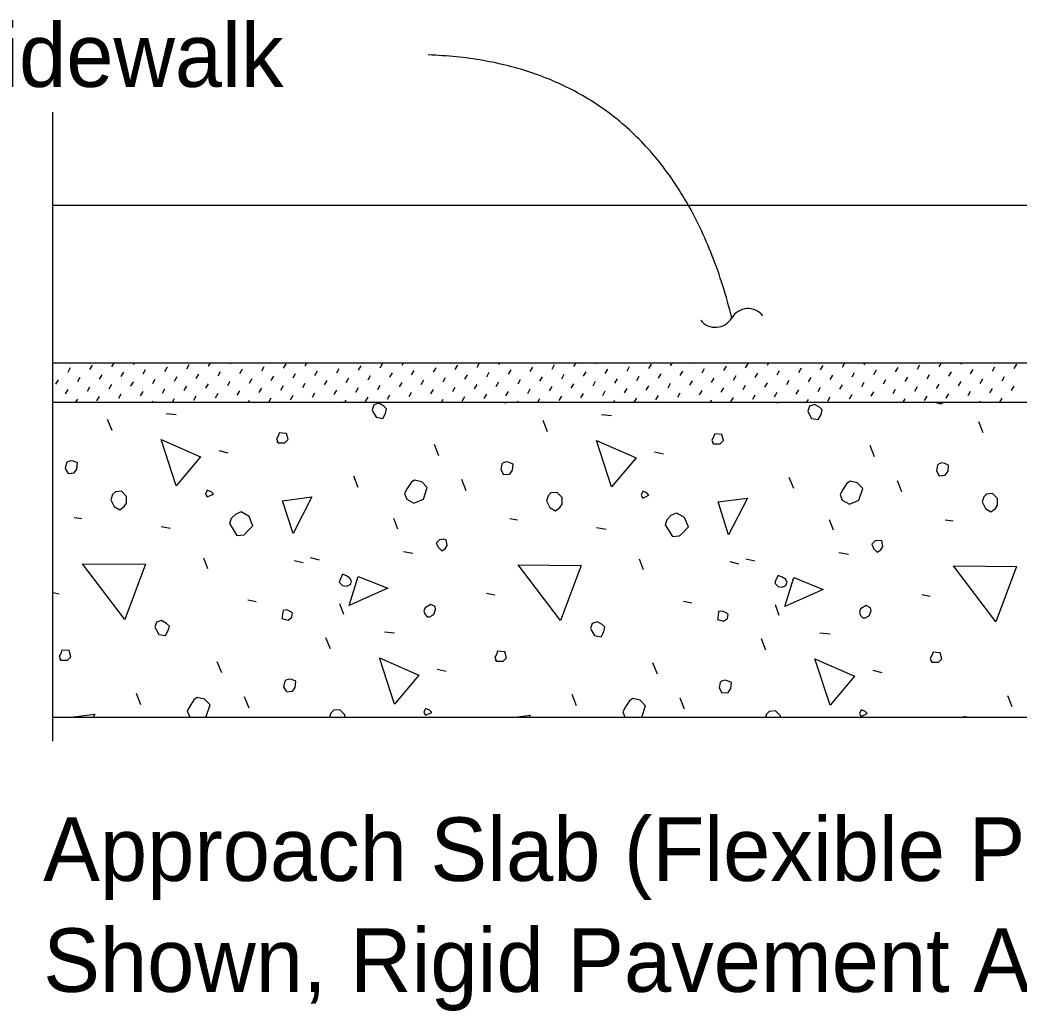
# Model space of a CAD drawing. Extents: x 0 to 40.8, y 1 to 28.
# Drawn here: x 23.621 to 26.792, y 9.097 to 12.242 of the extents above; entities that cross this region are included whole.
import ezdxf

# ---------------------------------------------------------------- set-up
doc = ezdxf.new("R2010")
doc.units = 0
for name, color, linetype in [('Dimension', 7, 'Continuous'), ('Miscellaneous', 7, 'Continuous'), ('TextStructures', 7, 'Continuous'), ('TrafBarrierConc', 7, 'Continuous')]:
    doc.layers.add(name, color=color, linetype=linetype)

msp = doc.modelspace()

# ---------------------------------------------------------------- linework, layer by layer
at = {"layer": 'Dimension'}
msp.add_lwpolyline([(23.7254, 9.9535), (23.7254, 11.9492)], dxfattribs=at)
for centre, start, end in [((25.9315, 11.2668), 38.2646, 149.9919), ((25.8282, 11.3265), 218.2646, 329.9919)]:
    msp.add_arc(centre, 0.0596, start, end, dxfattribs=at)
msp.add_open_spline([(25.8806, 11.2968), (25.6769, 12.1034), (24.917, 12.1314)], degree=2, dxfattribs=at)
at = {"layer": 'Miscellaneous'}
for p, q in [((23.7737, 11.1251), (23.7818, 11.1391)), ((23.8429, 11.1332), (23.851, 11.1472)), ((23.9121, 11.1413), (23.9197, 11.1545)), ((23.9812, 11.1494), (23.9842, 11.1545)), ((24.0117, 11.1189), (24.0198, 11.1328)), ((24.0809, 11.127), (24.089, 11.141)), ((24.1501, 11.1351), (24.1582, 11.1491)), ((24.2192, 11.1432), (24.2258, 11.1545)), ((24.2884, 11.1513), (24.2903, 11.1545)), ((24.3189, 11.1207), (24.327, 11.1347)), ((24.3881, 11.1288), (24.3962, 11.1428)), ((24.4573, 11.1369), (24.4654, 11.1509)), ((24.5264, 11.145), (24.5319, 11.1545)), ((24.5956, 11.1531), (24.5964, 11.1545)), ((24.6261, 11.1226), (24.6342, 11.1366)), ((24.6953, 11.1307), (24.7034, 11.1447)), ((24.7644, 11.1388), (24.7726, 11.1528)), ((24.8336, 11.1469), (24.838, 11.1545)), ((24.8641, 11.1164), (24.8722, 11.1304)), ((24.9333, 11.1245), (24.9414, 11.1385)), ((25.0025, 11.1326), (25.0106, 11.1466)), ((25.0716, 11.1407), (25.0796, 11.1545)), ((25.1408, 11.1488), (25.1441, 11.1545)), ((25.1713, 11.1183), (25.1794, 11.1323)), ((25.2405, 11.1264), (25.2486, 11.1404)), ((25.3097, 11.1345), (25.3178, 11.1485)), ((25.3788, 11.1426), (25.3857, 11.1545)), ((25.448, 11.1507), (25.4502, 11.1545)), ((25.4785, 11.1201), (25.4866, 11.1341)), ((25.5477, 11.1282), (25.5558, 11.1422)), ((25.6168, 11.1363), (25.6249, 11.1503)), ((25.686, 11.1444), (25.6918, 11.1545)), ((25.7552, 11.1526), (25.7563, 11.1545)), ((25.7857, 11.122), (25.7938, 11.136)), ((25.8549, 11.1301), (25.863, 11.1441)), ((25.924, 11.1382), (25.9321, 11.1522)), ((25.9932, 11.1463), (25.9979, 11.1545)), ((26.0237, 11.1158), (26.0318, 11.1298)), ((26.0624, 11.1544), (26.0624, 11.1545)), ((26.0929, 11.1239), (26.101, 11.1379)), ((26.1621, 11.132), (26.1702, 11.146)), ((26.2312, 11.1401), (26.2393, 11.1541)), ((26.3004, 11.1482), (26.304, 11.1545)), ((26.3309, 11.1177), (26.339, 11.1317)), ((26.4001, 11.1258), (26.4082, 11.1398)), ((26.4692, 11.1339), (26.4773, 11.1479)), ((26.5384, 11.142), (26.5457, 11.1545)), ((26.6076, 11.1501), (26.6101, 11.1545)), ((26.6381, 11.1196), (26.6462, 11.1335)), ((26.7073, 11.1277), (26.7154, 11.1417)), ((26.7764, 11.1358), (26.7845, 11.1498)), ((23.7351, 11.0864), (23.7432, 11.1004)), ((23.8043, 11.0945), (23.8124, 11.1085)), ((23.8734, 11.1026), (23.8815, 11.1166)), ((23.9426, 11.1108), (23.9507, 11.1247)), ((24.0423, 11.0883), (24.0504, 11.1023)), ((24.1114, 11.0964), (24.1195, 11.1104)), ((24.1806, 11.1045), (24.1887, 11.1185)), ((24.2498, 11.1126), (24.2579, 11.1266)), ((24.3495, 11.0902), (24.3576, 11.1042)), ((24.4186, 11.0983), (24.4267, 11.1123)), ((24.4878, 11.1064), (24.4959, 11.1204)), ((24.557, 11.1145), (24.5651, 11.1285)), ((24.5875, 11.084), (24.5956, 11.098)), ((24.6567, 11.0921), (24.6648, 11.1061)), ((24.7258, 11.1002), (24.7339, 11.1142)), ((24.795, 11.1083), (24.8031, 11.1223)), ((24.8947, 11.0859), (24.9028, 11.0998)), ((24.9638, 11.094), (24.9719, 11.108)), ((25.033, 11.1021), (25.0411, 11.1161)), ((25.1022, 11.1102), (25.1103, 11.1242)), ((25.2019, 11.0877), (25.21, 11.1017)), ((25.271, 11.0958), (25.2791, 11.1098)), ((25.3402, 11.1039), (25.3483, 11.1179)), ((25.4094, 11.112), (25.4175, 11.126)), ((25.509, 11.0896), (25.5171, 11.1036)), ((25.5782, 11.0977), (25.5863, 11.1117)), ((25.6474, 11.1058), (25.6555, 11.1198)), ((25.7165, 11.1139), (25.7246, 11.1279)), ((25.8162, 11.0915), (25.8243, 11.1055)), ((25.8854, 11.0996), (25.8935, 11.1136)), ((25.9546, 11.1077), (25.9627, 11.1217)), ((26.0543, 11.0853), (26.0624, 11.0993)), ((26.1234, 11.0934), (26.1315, 11.1074)), ((26.1926, 11.1015), (26.2007, 11.1155)), ((26.2617, 11.1096), (26.2698, 11.1236)), ((26.3614, 11.0871), (26.3695, 11.1011)), ((26.4306, 11.0952), (26.4387, 11.1092)), ((26.4998, 11.1033), (26.5079, 11.1173)), ((26.5689, 11.1115), (26.577, 11.1254)), ((26.6686, 11.089), (26.6767, 11.103)), ((26.7378, 11.0971), (26.7459, 11.1111)), ((23.7656, 11.0559), (23.7737, 11.0699)), ((23.8348, 11.064), (23.8429, 11.078)), ((23.904, 11.0721), (23.9121, 11.0861)), ((23.9731, 11.0802), (23.9812, 11.0942)), ((24.0728, 11.0578), (24.0809, 11.0718)), ((24.142, 11.0659), (24.1501, 11.0799)), ((24.2111, 11.074), (24.2192, 11.088)), ((24.2803, 11.0821), (24.2884, 11.0961)), ((24.38, 11.0597), (24.3881, 11.0737)), ((24.4492, 11.0678), (24.4573, 11.0818)), ((24.5183, 11.0759), (24.5264, 11.0899)), ((24.618, 11.0534), (24.6261, 11.0674)), ((24.6872, 11.0615), (24.6953, 11.0755)), ((24.7563, 11.0697), (24.7644, 11.0836)), ((24.8255, 11.0778), (24.8336, 11.0917)), ((24.9252, 11.0553), (24.9333, 11.0693)), ((24.9944, 11.0634), (25.0025, 11.0774)), ((25.0635, 11.0715), (25.0716, 11.0855)), ((25.1327, 11.0796), (25.1408, 11.0936)), ((25.2324, 11.0572), (25.2405, 11.0712)), ((25.3016, 11.0653), (25.3097, 11.0793)), ((25.3707, 11.0734), (25.3788, 11.0874)), ((25.4399, 11.0815), (25.448, 11.0955)), ((25.5396, 11.0591), (25.5477, 11.0731)), ((25.6087, 11.0672), (25.6168, 11.0812)), ((25.6779, 11.0753), (25.686, 11.0893)), ((25.7471, 11.0834), (25.7552, 11.0974)), ((25.7776, 11.0529), (25.7857, 11.0669)), ((25.8468, 11.061), (25.8549, 11.075)), ((25.9159, 11.0691), (25.924, 11.0831)), ((25.9851, 11.0772), (25.9932, 11.0912)), ((26.0848, 11.0547), (26.0929, 11.0687)), ((26.1539, 11.0628), (26.1621, 11.0768)), ((26.2231, 11.0709), (26.2312, 11.0849)), ((26.2923, 11.079), (26.3004, 11.093)), ((26.392, 11.0566), (26.4001, 11.0706)), ((26.4611, 11.0647), (26.4692, 11.0787)), ((26.5303, 11.0728), (26.5384, 11.0868)), ((26.5995, 11.0809), (26.6076, 11.0949)), ((26.6992, 11.0585), (26.7073, 11.0725)), ((26.7683, 11.0666), (26.7764, 11.0806)), ((23.7985, 11.0295), (23.8043, 11.0394)), ((23.8653, 11.0335), (23.8734, 11.0475)), ((23.9345, 11.0416), (23.9426, 11.0556)), ((24.0036, 11.0497), (24.0117, 11.0637)), ((24.1046, 11.0295), (24.1114, 11.0413)), ((24.1725, 11.0354), (24.1806, 11.0494)), ((24.2417, 11.0435), (24.2498, 11.0575)), ((24.3108, 11.0516), (24.3189, 11.0656)), ((24.3463, 11.0295), (24.3495, 11.035)), ((24.4107, 11.0295), (24.4186, 11.0431)), ((24.4797, 11.0372), (24.4878, 11.0512)), ((24.5489, 11.0453), (24.557, 11.0593)), ((24.6524, 11.0295), (24.6567, 11.0369)), ((24.7177, 11.031), (24.7258, 11.045)), ((24.7869, 11.0391), (24.795, 11.0531)), ((24.856, 11.0472), (24.8641, 11.0612)), ((24.9585, 11.0295), (24.9638, 11.0388)), ((25.0249, 11.0329), (25.033, 11.0469)), ((25.0941, 11.041), (25.1022, 11.055)), ((25.1632, 11.0491), (25.1713, 11.0631)), ((25.2646, 11.0295), (25.271, 11.0407)), ((25.3321, 11.0348), (25.3402, 11.0488)), ((25.4012, 11.0429), (25.4094, 11.0569)), ((25.4704, 11.051), (25.4785, 11.065)), ((25.5062, 11.0295), (25.509, 11.0344)), ((25.5707, 11.0295), (25.5782, 11.0425)), ((25.6393, 11.0367), (25.6474, 11.0506)), ((25.7084, 11.0448), (25.7165, 11.0587)), ((25.8123, 11.0295), (25.8162, 11.0363)), ((25.8773, 11.0304), (25.8854, 11.0444)), ((25.9465, 11.0385), (25.9546, 11.0525)), ((26.0156, 11.0466), (26.0237, 11.0606)), ((26.1184, 11.0295), (26.1234, 11.0382)), ((26.1845, 11.0323), (26.1926, 11.0463)), ((26.2536, 11.0404), (26.2617, 11.0544)), ((26.3228, 11.0485), (26.3309, 11.0625)), ((26.4245, 11.0295), (26.4306, 11.0401)), ((26.4917, 11.0342), (26.4998, 11.0482)), ((26.5608, 11.0423), (26.5689, 11.0563)), ((26.63, 11.0504), (26.6381, 11.0644)), ((26.7306, 11.0295), (26.7378, 11.042)), ((23.7341, 11.0295), (23.7351, 11.0313)), ((24.0402, 11.0295), (24.0423, 11.0332)), ((24.894, 11.0295), (24.8947, 11.0307)), ((25.2001, 11.0295), (25.2019, 11.0326)), ((26.0539, 11.0295), (26.0543, 11.0301)), ((26.36, 11.0295), (26.3614, 11.032)), ((26.6661, 11.0295), (26.6686, 11.0339)), ((23.9131, 10.9391), (23.899, 10.9745)), ((24.0846, 10.9939), (24.1164, 10.9904)), ((25.2955, 10.9356), (25.2814, 10.971)), ((25.467, 10.9904), (25.4988, 10.9869)), ((26.6779, 10.9321), (26.6638, 10.9674)), ((24.2525, 10.8755), (24.2808, 10.8684)), ((24.9508, 10.8596), (24.9366, 10.895)), ((26.3332, 10.8561), (26.319, 10.8914)), ((25.6349, 10.872), (25.6632, 10.8649)), ((24.6945, 10.7588), (24.6803, 10.7942)), ((25.0374, 10.7482), (25.0233, 10.7836)), ((26.0769, 10.7553), (26.0627, 10.7907)), ((26.4198, 10.7447), (26.4057, 10.78)), ((23.7929, 10.6634), (23.8177, 10.6598)), ((24.82, 10.6263), (24.8076, 10.6598)), ((25.1753, 10.6598), (25.2, 10.6563)), ((26.2024, 10.6227), (26.19, 10.6563)), ((26.5577, 10.6563), (26.5824, 10.6528)), ((24.0687, 10.6351), (24.0987, 10.6298)), ((25.4511, 10.6316), (25.4811, 10.6263)), ((24.2172, 10.5007), (24.2048, 10.5343)), ((24.4912, 10.5273), (24.5195, 10.5202)), ((24.5424, 10.5361), (24.5707, 10.529)), ((24.8377, 10.5555), (24.8677, 10.5502)), ((25.5996, 10.4972), (25.5872, 10.5308)), ((25.9248, 10.5326), (25.9531, 10.5255)), ((26.22, 10.552), (26.2501, 10.5467)), ((25.8736, 10.5237), (25.9018, 10.5166)), ((23.7254, 10.4251), (23.7452, 10.4212)), ((24.3444, 10.4017), (24.371, 10.3964)), ((25.1011, 10.423), (25.1276, 10.4177)), ((26.4834, 10.4194), (26.51, 10.4141)), ((24.6485, 10.3558), (24.6361, 10.3894)), ((25.7268, 10.3982), (25.7534, 10.3929)), ((26.0309, 10.3522), (26.0185, 10.3858)), ((24.6061, 10.2462), (24.5919, 10.2815)), ((24.7775, 10.301), (24.8094, 10.2974)), ((25.9885, 10.2426), (25.9743, 10.278)), ((26.1599, 10.2974), (26.1918, 10.2939)), ((24.2614, 10.1702), (24.2472, 10.2055)), ((24.9455, 10.1825), (24.9738, 10.1755)), ((25.6438, 10.1666), (25.6296, 10.202)), ((26.3279, 10.179), (26.3562, 10.1719)), ((24.005, 10.0694), (23.9909, 10.1048)), ((24.348, 10.0588), (24.3338, 10.0942)), ((25.3874, 10.0659), (25.3733, 10.1012)), ((25.7304, 10.0553), (25.7162, 10.0906)), ((26.7698, 10.0623), (26.7557, 10.0977))]:
    msp.add_line(p, q, dxfattribs=at)
for points in [[(24.6432, 11.0293), (24.643, 11.0295)], [(24.6433, 11.0295), (24.6432, 11.0293)], [(24.7422, 10.9975), (24.751, 10.9816), (24.7722, 10.978), (24.7811, 10.9939), (24.7846, 11.0081), (24.7758, 11.0169), (24.7599, 11.0258), (24.744, 11.0205), (24.7387, 11.0046), (24.7422, 10.9975)], [(25.1539, 11.0295), (25.1612, 11.0275), (25.1639, 11.0295)], [(26.0256, 11.0258), (26.0227, 11.0295)], [(26.027, 11.0295), (26.0256, 11.0258)], [(26.1246, 10.9939), (26.1334, 10.978), (26.1546, 10.9745), (26.1635, 10.9904), (26.167, 11.0046), (26.1582, 11.0134), (26.1423, 11.0222), (26.1264, 11.0169), (26.1211, 11.001), (26.1246, 10.9939)], [(26.5241, 11.0293), (26.5435, 11.024), (26.5513, 11.0295)], [(26.5241, 11.0295), (26.5241, 11.0293)], [(24.1164, 10.7641), (24.0687, 10.9109), (24.1942, 10.8561), (24.1164, 10.7641)], [(24.4399, 10.9003), (24.4611, 10.9003), (24.4717, 10.9109), (24.4664, 10.9303), (24.4434, 10.9321), (24.4399, 10.9215), (24.4346, 10.9126), (24.4399, 10.9003), (24.4364, 10.9038)], [(25.4988, 10.7606), (25.4511, 10.9073), (25.5766, 10.8525), (25.4988, 10.7606)], [(25.8223, 10.8967), (25.8435, 10.8967), (25.8541, 10.9073), (25.8488, 10.9268), (25.8258, 10.9285), (25.8223, 10.9179), (25.817, 10.9091), (25.8223, 10.8967), (25.8188, 10.9003)], [(23.7646, 10.8189), (23.7735, 10.803), (23.7929, 10.8048), (23.8017, 10.8172), (23.8035, 10.8366), (23.7911, 10.8419), (23.7823, 10.8437), (23.7717, 10.8402), (23.7682, 10.8366), (23.7646, 10.8189)], [(25.147, 10.8154), (25.1559, 10.7995), (25.1753, 10.8013), (25.1841, 10.8136), (25.1859, 10.8331), (25.1735, 10.8384), (25.1647, 10.8402), (25.1541, 10.8366), (25.1505, 10.8331), (25.147, 10.8154)], [(26.5294, 10.8119), (26.5382, 10.796), (26.5577, 10.7977), (26.5665, 10.8101), (26.5683, 10.8295), (26.5559, 10.8348), (26.5471, 10.8366), (26.5365, 10.8331), (26.5329, 10.8295), (26.5294, 10.8119)], [(24.8483, 10.7217), (24.8712, 10.7093), (24.9013, 10.7217), (24.9137, 10.7588), (24.896, 10.7765), (24.873, 10.7818), (24.8624, 10.7747), (24.85, 10.7553), (24.8412, 10.7394), (24.8483, 10.7217)], [(24.2154, 10.7288), (24.2348, 10.7376), (24.2278, 10.7447), (24.2154, 10.75), (24.2101, 10.7376), (24.2154, 10.7288)], [(26.2307, 10.7182), (26.2536, 10.7058), (26.2837, 10.7182), (26.2961, 10.7553), (26.2784, 10.773), (26.2554, 10.7783), (26.2448, 10.7712), (26.2324, 10.7518), (26.2236, 10.7359), (26.2307, 10.7182)], [(23.9096, 10.7199), (23.9202, 10.6987), (23.9379, 10.6881), (23.952, 10.6987), (23.9591, 10.7093), (23.9591, 10.7305), (23.9432, 10.7465), (23.9237, 10.7447), (23.9149, 10.7359), (23.9096, 10.7199)], [(24.4876, 10.6121), (24.454, 10.7164), (24.5477, 10.7288), (24.4876, 10.6121)], [(25.292, 10.7164), (25.3026, 10.6952), (25.3203, 10.6846), (25.3344, 10.6952), (25.3415, 10.7058), (25.3415, 10.727), (25.3256, 10.7429), (25.3061, 10.7412), (25.2973, 10.7323), (25.292, 10.7164)], [(25.5978, 10.7252), (25.6172, 10.7341), (25.6102, 10.7412), (25.5978, 10.7465), (25.5925, 10.7341), (25.5978, 10.7252)], [(25.87, 10.6086), (25.8364, 10.7129), (25.9301, 10.7252), (25.87, 10.6086)], [(26.6744, 10.7129), (26.685, 10.6917), (26.7026, 10.6811), (26.7168, 10.6917), (26.7239, 10.7023), (26.7239, 10.7235), (26.708, 10.7394), (26.6885, 10.7376), (26.6797, 10.7288), (26.6744, 10.7129)], [(24.2861, 10.6439), (24.3091, 10.6068), (24.3321, 10.6086), (24.3409, 10.6174), (24.3604, 10.6369), (24.348, 10.6669), (24.3232, 10.6811), (24.3056, 10.674), (24.2914, 10.6598), (24.2861, 10.6439)], [(25.6685, 10.6404), (25.6915, 10.6033), (25.7145, 10.605), (25.7233, 10.6139), (25.7428, 10.6333), (25.7304, 10.6634), (25.7056, 10.6775), (25.6879, 10.6704), (25.6738, 10.6563), (25.6685, 10.6404)], [(24.949, 10.5679), (24.9596, 10.5573), (24.9702, 10.5644), (24.9773, 10.575), (24.9738, 10.5927), (24.9649, 10.5944), (24.9526, 10.5927), (24.942, 10.5821), (24.949, 10.5679)], [(26.3314, 10.5644), (26.342, 10.5538), (26.3526, 10.5608), (26.3597, 10.5714), (26.3562, 10.5891), (26.3473, 10.5909), (26.335, 10.5891), (26.3243, 10.5785), (26.3314, 10.5644)], [(23.9538, 10.3399), (23.8194, 10.5166), (24.0192, 10.5149), (23.9538, 10.3399)], [(25.3362, 10.3363), (25.2018, 10.5131), (25.4016, 10.5113), (25.3362, 10.3363)], [(26.7186, 10.3328), (26.5842, 10.5096), (26.784, 10.5078), (26.7186, 10.3328)], [(24.645, 10.4477), (24.6573, 10.4459), (24.6697, 10.4512), (24.6733, 10.4618), (24.6679, 10.4707), (24.6573, 10.4778), (24.645, 10.4831), (24.6379, 10.4689), (24.6344, 10.4583), (24.645, 10.4477)], [(24.6662, 10.3841), (24.6945, 10.476), (24.7882, 10.4389), (24.6662, 10.3841)], [(26.0274, 10.4442), (26.0397, 10.4424), (26.0521, 10.4477), (26.0556, 10.4583), (26.0503, 10.4672), (26.0397, 10.4742), (26.0274, 10.4795), (26.0203, 10.4654), (26.0168, 10.4548), (26.0274, 10.4442)], [(26.0486, 10.3805), (26.0769, 10.4725), (26.1705, 10.4353), (26.0486, 10.3805)], [(24.4523, 10.3434), (24.4717, 10.3381), (24.4841, 10.3469), (24.4859, 10.3593), (24.4823, 10.3629), (24.4682, 10.3699), (24.4558, 10.3682), (24.454, 10.3558), (24.4523, 10.3434)], [(24.9137, 10.3487), (24.9207, 10.3487), (24.9349, 10.3558), (24.9402, 10.3717), (24.9384, 10.3805), (24.9243, 10.3876), (24.9066, 10.377), (24.9031, 10.3664), (24.9066, 10.3558), (24.9137, 10.3487)], [(26.2961, 10.3452), (26.3031, 10.3452), (26.3173, 10.3522), (26.3226, 10.3682), (26.3208, 10.377), (26.3067, 10.3841), (26.289, 10.3735), (26.2855, 10.3629), (26.289, 10.3522), (26.2961, 10.3452)], [(25.8347, 10.3399), (25.8541, 10.3346), (25.8665, 10.3434), (25.8683, 10.3558), (25.8647, 10.3593), (25.8506, 10.3664), (25.8382, 10.3646), (25.8364, 10.3522), (25.8347, 10.3399)], [(24.0528, 10.3081), (24.0616, 10.2921), (24.0828, 10.2886), (24.0917, 10.3045), (24.0952, 10.3187), (24.0864, 10.3275), (24.0704, 10.3363), (24.0545, 10.331), (24.0492, 10.3151), (24.0528, 10.3081)], [(25.4352, 10.3045), (25.444, 10.2886), (25.4652, 10.2851), (25.474, 10.301), (25.4776, 10.3151), (25.4687, 10.324), (25.4528, 10.3328), (25.4369, 10.3275), (25.4316, 10.3116), (25.4352, 10.3045)], [(23.7505, 10.2108), (23.7717, 10.2108), (23.7823, 10.2214), (23.777, 10.2409), (23.754, 10.2426), (23.7505, 10.232), (23.7452, 10.2232), (23.7505, 10.2108), (23.7469, 10.2144)], [(24.8094, 10.0712), (24.7616, 10.2179), (24.8872, 10.1631), (24.8094, 10.0712)], [(25.1329, 10.2073), (25.1541, 10.2073), (25.1647, 10.2179), (25.1594, 10.2373), (25.1364, 10.2391), (25.1329, 10.2285), (25.1276, 10.2197), (25.1329, 10.2073), (25.1293, 10.2108)], [(26.1918, 10.0676), (26.144, 10.2144), (26.2695, 10.1596), (26.1918, 10.0676)], [(26.5153, 10.2038), (26.5365, 10.2038), (26.5471, 10.2144), (26.5418, 10.2338), (26.5188, 10.2356), (26.5153, 10.225), (26.51, 10.2161), (26.5153, 10.2038), (26.5117, 10.2073)], [(24.4576, 10.126), (24.4664, 10.1101), (24.4859, 10.1118), (24.4947, 10.1242), (24.4965, 10.1437), (24.4841, 10.149), (24.4753, 10.1507), (24.4647, 10.1472), (24.4611, 10.1437), (24.4576, 10.126)], [(25.84, 10.1224), (25.8488, 10.1065), (25.8683, 10.1083), (25.8771, 10.1207), (25.8789, 10.1401), (25.8665, 10.1454), (25.8577, 10.1472), (25.847, 10.1437), (25.8435, 10.1401), (25.84, 10.1224)], [(24.2052, 10.0295), (24.2119, 10.0323), (24.2242, 10.0694), (24.2066, 10.0871), (24.1836, 10.0924), (24.173, 10.0853), (24.1606, 10.0659), (24.1518, 10.05), (24.1588, 10.0323)], [(25.5945, 10.0295), (25.6066, 10.0659), (25.589, 10.0835), (25.566, 10.0888), (25.5554, 10.0818), (25.543, 10.0623), (25.5342, 10.0464), (25.5409, 10.0295)], [(24.652, 10.0295), (24.652, 10.0376), (24.6361, 10.0535), (24.6167, 10.0517), (24.6078, 10.0429), (24.6034, 10.0295)], [(24.9084, 10.0358), (24.9278, 10.0447), (24.9207, 10.0517), (24.9084, 10.057), (24.9031, 10.0447), (24.9084, 10.0358)], [(26.2908, 10.0323), (26.3102, 10.0411), (26.3031, 10.0482), (26.2908, 10.0535), (26.2855, 10.0411), (26.2908, 10.0323)], [(23.7839, 10.0295), (23.8583, 10.0394), (23.8532, 10.0295)], [(24.1588, 10.0323), (24.164, 10.0295)], [(25.193, 10.0295), (25.2407, 10.0358), (25.2375, 10.0295)], [(26.0344, 10.0295), (26.0344, 10.034), (26.0185, 10.05), (25.9991, 10.0482), (25.9902, 10.0394), (25.987, 10.0295)], [(26.6022, 10.0295), (26.6231, 10.0323), (26.6217, 10.0295)]]:
    msp.add_lwpolyline(points, dxfattribs=at)
at = {"layer": 'TrafBarrierConc'}
for p, q in [((23.7254, 11.6545), (39.5565, 11.6545)), ((23.7254, 11.1545), (39.5565, 11.1545)), ((23.7254, 11.0295), (39.5565, 11.0295)), ((23.7254, 10.0295), (39.5565, 10.0295))]:
    msp.add_line(p, q, dxfattribs=at)

# ---------------------------------------------------------------- texts
at = {"layer": 'Dimension'}
for s, p in [('Approach Slab (Flexible Pavement Approach Slab ', (23.6948, 9.5101)), ('Shown, Rigid Pavement Approach Slab Similar)', (23.6948, 9.1581))]:
    msp.add_text(s, height=0.2016, dxfattribs=at).set_placement(p)
at = {"layer": 'TextStructures'}
msp.add_text('Raised Sidewalk', height=0.2016, dxfattribs=at).set_placement((22.4642, 12.0298))

doc.saveas('drawing.dxf')
